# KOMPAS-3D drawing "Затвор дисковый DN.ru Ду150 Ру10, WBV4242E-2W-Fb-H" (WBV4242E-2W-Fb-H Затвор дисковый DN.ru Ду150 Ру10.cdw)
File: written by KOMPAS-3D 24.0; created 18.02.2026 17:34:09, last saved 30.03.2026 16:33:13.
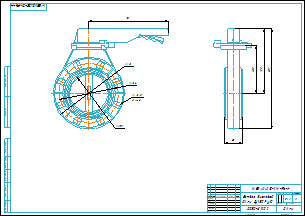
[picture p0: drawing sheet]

Document properties: Автор: R2D2; Форматы листов документа: A2; Полное имя файла: WBV4242E-2W-Fb-H Затвор дисковый DN.ru Ду150 Ру10.m3d; Масса: 5.01; Наименование: Затвор дисковый DN.ru Ду150 Ру10; Количество листов документа: 1; Примечание: D050-81202

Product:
- Part/product: Затвор дисковый DN.ru Ду150 Ру10  | designation WBV4242E-2W-Fb-H
    Масса: 5.01
    Раздел спецификации: Прочие изделия
    Примечание: D050-81202

Views: Проекционный вид 2
Referenced files in E:\Работа\Зайцев\WBV4242E-2W-Fb-ISO Затвор дисковый DN.ru Ду50-200 Ру10\DN150\: WBV4242E-2W-Fb-ISO Затвор дисковый DN.ru Ду150 Ру10.m3d
Referenced files in E:\Работа\Зайцев\Для компаса\: чертеж DN.ru А3.cdt
Referenced files in E:\Работа\Зайцев\WBV4242E-2W-Fb-H Затвор дисковый DN.ru Ду50-200 Ру10\DN150\: WBV4242E-2W-Fb-H Затвор дисковый DN.ru Ду150 Ру10.m3d
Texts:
  WBV4242E-2W-Fb-H
  чертеж DN.ru А3.cdt
  Затвор дисковый
  DN.ru Ду150 Ру10
  Затвор дисковый DN.ru Ду150 Ру10
  WBV4242E-2W-Fb-H Затвор дисковый DN.ru Ду150 Ру10
Dimensions and other numbers on the sheet: 0; 3; 4; 185; 69; 253; 391; 8; 1:2; 1; 2; 5,01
